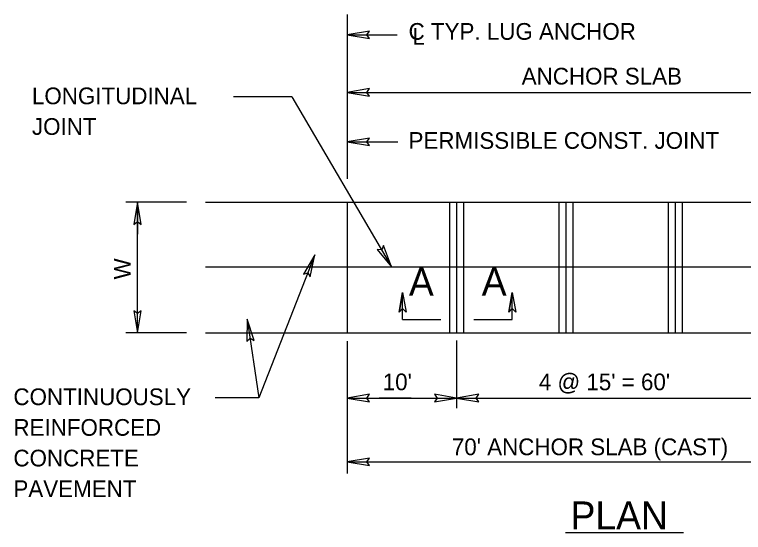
# Model space of a CAD drawing. Extents: x 3.1 to 10.2, y 1.2 to 11.3.
# Drawn here: x 4.302 to 6.918, y 9.41 to 11.268 of the extents above; entities that cross this region are included whole.
import ezdxf

# ---------------------------------------------------------------- set-up
doc = ezdxf.new("R2010")
doc.units = 0
for name, color, linetype in [('DETL-DIMS', 7, 'Continuous'), ('DETL-LINE', 7, 'Continuous'), ('DETL-NOTE', 7, 'Continuous'), ('DETL-TITL', 7, 'Continuous')]:
    doc.layers.add(name, color=color, linetype=linetype)

msp = doc.modelspace()

# ---------------------------------------------------------------- linework, layer by layer
at = {"layer": 'DETL-DIMS'}
for p, q in [((5.4958, 11.2684), (5.4958, 10.6785)), ((5.5756, 11.2092), (5.4958, 11.1958)), ((5.5756, 11.2092), (5.4958, 11.1958)), ((5.5656, 11.1958), (5.5756, 11.2092)), ((5.5656, 11.1958), (5.5756, 11.2092)), ((5.4958, 11.1958), (5.6752, 11.1958)), ((5.4958, 11.1958), (5.6425, 11.1958)), ((5.4958, 11.1958), (5.5756, 11.1826)), ((5.4958, 11.1958), (5.5756, 11.1826)), ((5.5756, 11.1826), (5.5656, 11.1958)), ((5.5756, 11.1826), (5.5656, 11.1958)), ((5.5756, 11.0027), (5.4958, 10.9893)), ((5.5756, 11.0027), (5.4958, 10.9893)), ((5.4958, 10.9893), (7.4583, 10.9893)), ((5.4958, 10.9893), (5.6425, 10.9893)), ((5.4958, 10.9893), (5.5756, 10.9761)), ((5.4958, 10.9893), (5.5756, 10.9761)), ((5.5656, 10.9893), (5.5756, 11.0027)), ((5.5656, 10.9893), (5.5756, 11.0027)), ((5.5756, 10.9761), (5.5656, 10.9893)), ((5.5756, 10.9761), (5.5656, 10.9893)), ((5.2973, 10.9735), (5.0877, 10.9735)), ((5.2973, 10.9735), (5.655, 10.3635)), ((5.5756, 10.8253), (5.4958, 10.8119)), ((5.5756, 10.8253), (5.4958, 10.8119)), ((5.4958, 10.8119), (5.6773, 10.8119)), ((5.4958, 10.8119), (5.6425, 10.8119)), ((5.4958, 10.8119), (5.5756, 10.7987)), ((5.4958, 10.8119), (5.5756, 10.7987)), ((5.5656, 10.8119), (5.5756, 10.8253)), ((5.5656, 10.8119), (5.5756, 10.8253)), ((5.5756, 10.7987), (5.5656, 10.8119)), ((5.5756, 10.7987), (5.5656, 10.8119)), ((4.9184, 10.595), (4.7013, 10.595)), ((4.7428, 10.595), (4.7295, 10.5152)), ((4.7428, 10.595), (4.7295, 10.5152)), ((4.7428, 10.1258), (4.7428, 10.595)), ((4.7428, 10.595), (4.7428, 10.4803)), ((4.7561, 10.5153), (4.7428, 10.595)), ((4.7561, 10.5153), (4.7428, 10.595)), ((4.7295, 10.5152), (4.7428, 10.5253)), ((4.7295, 10.5152), (4.7428, 10.5253)), ((4.7428, 10.5253), (4.7561, 10.5153)), ((4.7428, 10.5253), (4.7561, 10.5153)), ((5.6261, 10.4391), (5.6198, 10.4237)), ((5.6261, 10.4391), (5.6198, 10.4237)), ((5.655, 10.3635), (5.6261, 10.4391)), ((5.655, 10.3635), (5.6261, 10.4391)), ((5.6198, 10.4237), (5.6031, 10.4256)), ((5.6031, 10.4256), (5.655, 10.3635)), ((5.6198, 10.4237), (5.6031, 10.4256)), ((5.6031, 10.4256), (5.655, 10.3635)), ((5.3797, 10.4064), (5.1786, 9.8929)), ((5.3797, 10.4064), (5.3383, 10.3369)), ((5.3797, 10.4064), (5.3383, 10.3369)), ((5.3631, 10.3273), (5.3797, 10.4064)), ((5.3631, 10.3273), (5.3797, 10.4064)), ((5.3383, 10.3369), (5.3543, 10.3415)), ((5.3383, 10.3369), (5.3543, 10.3415)), ((5.3543, 10.3415), (5.3631, 10.3273)), ((5.3543, 10.3415), (5.3631, 10.3273)), ((4.7428, 10.1258), (4.7428, 10.2725)), ((5.6943, 10.2714), (5.6817, 10.1999)), ((5.6943, 10.1739), (5.6943, 10.2714)), ((5.6943, 10.2714), (5.7069, 10.1999)), ((6.0882, 10.2714), (6.0756, 10.1999)), ((6.0882, 10.1739), (6.0882, 10.2714)), ((6.0882, 10.2714), (6.1008, 10.1999)), ((4.7428, 10.1956), (4.7294, 10.2056)), ((4.7294, 10.2056), (4.7428, 10.1258)), ((4.7428, 10.1956), (4.7294, 10.2056)), ((4.7294, 10.2056), (4.7428, 10.1258)), ((4.7428, 10.1258), (4.756, 10.2056)), ((4.756, 10.2056), (4.7428, 10.1956)), ((4.7428, 10.1258), (4.756, 10.2056)), ((4.756, 10.2056), (4.7428, 10.1956)), ((5.6817, 10.1999), (5.6943, 10.2134)), ((5.6943, 10.2134), (5.7069, 10.1999)), ((6.0756, 10.1999), (6.0882, 10.2134)), ((6.0882, 10.2134), (6.1008, 10.1999)), ((5.1365, 10.1757), (5.1352, 10.0948)), ((5.1365, 10.1757), (5.1352, 10.0948)), ((5.1615, 10.0988), (5.1365, 10.1757)), ((5.1615, 10.0988), (5.1365, 10.1757)), ((5.1365, 10.1757), (5.1786, 9.8929)), ((5.6943, 10.1739), (5.8322, 10.1739)), ((5.9503, 10.1739), (6.0882, 10.1739)), ((4.9184, 10.1258), (4.7013, 10.1258)), ((5.1352, 10.0948), (5.1468, 10.1067)), ((5.1352, 10.0948), (5.1468, 10.1067)), ((5.1468, 10.1067), (5.1615, 10.0988)), ((5.1468, 10.1067), (5.1615, 10.0988)), ((5.8883, 10.0987), (5.8883, 9.856)), ((5.4958, 10.0966), (5.4958, 9.6211)), ((5.1786, 9.8929), (5.0223, 9.8929)), ((5.5756, 9.9056), (5.4958, 9.8922)), ((5.5756, 9.9056), (5.4958, 9.8922)), ((5.4958, 9.8922), (5.7252, 9.8922)), ((5.4958, 9.8922), (5.5756, 9.879)), ((5.4958, 9.8922), (5.5756, 9.879)), ((5.4958, 9.8922), (5.6425, 9.8922)), ((5.5656, 9.8922), (5.5756, 9.9056)), ((5.5656, 9.8922), (5.5756, 9.9056)), ((5.5756, 9.879), (5.5656, 9.8922)), ((5.5756, 9.879), (5.5656, 9.8922)), ((5.7252, 9.8922), (5.6105, 9.8922)), ((5.7252, 9.8922), (7.4583, 9.8922)), ((5.7252, 9.8922), (5.8719, 9.8922)), ((5.8883, 9.8922), (5.8085, 9.9055)), ((5.8085, 9.9055), (5.8186, 9.8922)), ((5.8883, 9.8922), (5.8085, 9.9055)), ((5.8085, 9.9055), (5.8186, 9.8922)), ((5.8186, 9.8922), (5.8086, 9.8788)), ((5.8086, 9.8788), (5.8883, 9.8922)), ((5.8186, 9.8922), (5.8086, 9.8788)), ((5.8086, 9.8788), (5.8883, 9.8922)), ((5.9681, 9.9056), (5.8883, 9.8922)), ((5.9681, 9.9056), (5.8883, 9.8922)), ((5.8883, 9.8922), (5.9681, 9.879)), ((5.8883, 9.8922), (5.9681, 9.879)), ((5.9581, 9.8922), (5.9681, 9.9056)), ((5.9581, 9.8922), (5.9681, 9.9056)), ((5.9681, 9.879), (5.9581, 9.8922)), ((5.9681, 9.879), (5.9581, 9.8922)), ((5.5756, 9.6762), (5.4958, 9.6628)), ((5.5756, 9.6762), (5.4958, 9.6628)), ((5.4958, 9.6628), (7.4583, 9.6628)), ((5.4958, 9.6628), (5.5756, 9.6495)), ((5.4958, 9.6628), (5.5756, 9.6495)), ((5.5656, 9.6628), (5.5756, 9.6762)), ((5.5656, 9.6628), (5.5756, 9.6762)), ((5.5756, 9.6495), (5.5656, 9.6628)), ((5.5756, 9.6495), (5.5656, 9.6628))]:
    msp.add_line(p, q, dxfattribs=at)
for points in [[(5.6817, 10.1999), (5.6943, 10.2714), (5.7069, 10.1999), (5.6943, 10.2134)], [(6.0756, 10.1999), (6.0882, 10.2714), (6.1008, 10.1999), (6.0882, 10.2134)]]:
    msp.add_lwpolyline(points, close=True, dxfattribs=at)
at = {"layer": 'DETL-LINE'}
for p, q in [((6.2558, 10.5956), (6.2558, 10.1263)), ((6.2808, 10.5956), (6.2808, 10.1263)), ((6.3058, 10.5956), (6.3058, 10.1263)), ((6.6483, 10.5961), (6.6483, 10.1268)), ((6.6733, 10.5961), (6.6733, 10.1268)), ((6.6983, 10.5961), (6.6983, 10.1268)), ((4.9869, 10.595), (8.1382, 10.595)), ((5.4958, 10.595), (5.4958, 10.1258)), ((5.8633, 10.595), (5.8633, 10.1258)), ((5.8883, 10.595), (5.8883, 10.1258)), ((5.9133, 10.595), (5.9133, 10.1258)), ((4.9869, 10.3635), (8.1382, 10.3635)), ((4.9869, 10.1258), (8.1382, 10.1258))]:
    msp.add_line(p, q, dxfattribs=at)
at = {"layer": 'DETL-TITL'}
msp.add_line((6.2791, 9.4099), (6.7031, 9.4099), dxfattribs=at)

# ---------------------------------------------------------------- texts
at = {"layer": 'DETL-NOTE'}
for s, p in [('C TYP. LUG ANCHOR', (5.7159, 11.178)), ('ANCHOR SLAB', (6.1221, 11.0174)), ('LONGITUDINAL', (4.3641, 10.9467)), ('JOINT', (4.3641, 10.8367)), ('PERMISSIBLE CONST. JOINT', (5.7159, 10.7866)), ("10'", (5.6232, 9.9201)), ("4 @ 15' = 60'", (6.1835, 9.9201)), ('CONTINUOUSLY', (4.2976, 9.8667)), ('REINFORCED', (4.2976, 9.7567)), ('CONCRETE', (4.2976, 9.6467)), ('PAVEMENT', (4.2976, 9.5367))]:
    msp.add_text(s, height=0.06, dxfattribs=at).set_placement(p)
for s, rotation, p in [('L', 360, (5.7295, 11.1599)), ('W', 90, (4.7185, 10.3178)), ("70' ANCHOR SLAB (CAST)", 360, (5.8713, 9.687))]:
    msp.add_text(s, height=0.06, rotation=rotation, dxfattribs=at).set_placement(p)
at = {"layer": 'DETL-TITL'}
for p in [(5.9786, 10.2602), (5.7172, 10.2596)]:
    msp.add_text('A', height=0.1, dxfattribs=at).set_placement(p)
msp.add_text('PLAN', height=0.1, rotation=360, dxfattribs=at).set_placement((6.2974, 9.421))

doc.saveas('drawing.dxf')
